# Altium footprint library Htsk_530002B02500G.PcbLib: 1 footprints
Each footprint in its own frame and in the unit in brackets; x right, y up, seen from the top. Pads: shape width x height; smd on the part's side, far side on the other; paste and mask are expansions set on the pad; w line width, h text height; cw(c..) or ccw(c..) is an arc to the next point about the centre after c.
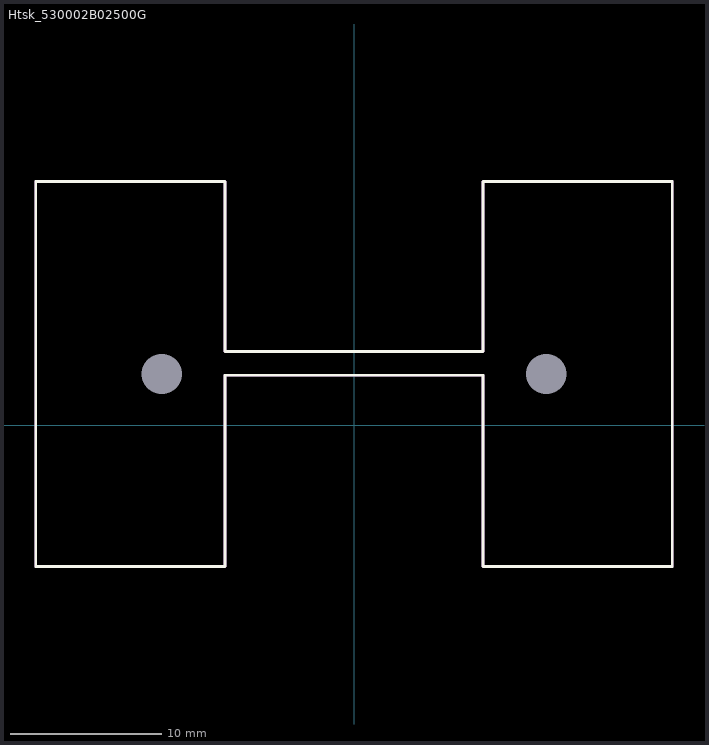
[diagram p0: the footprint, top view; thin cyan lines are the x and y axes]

## Htsk_530002B02500G [mm]
height 63.5
pads (2):
  round 0 hole 2.67 unplated mask+0: 0(-12.7,3.381) 0(12.7,3.381)
Top Overlay:
  lines w0.178: -20.995,-9.319 -20.995,16.081 -8.51,16.081 -8.51,4.872 8.51,4.872 8.51,16.081 20.995,16.081 20.995,-9.319 8.51,-9.319 8.51,3.302 -8.51,3.302 -8.51,-9.319 -20.995,-9.319
M5 Assembly Top:
  text ".Designator" at -1.524,2.873 h1.02
M13 Component Bodies Top:
  lines w0.178: -20.995,-9.319 -8.51,-9.319 -8.51,3.302 8.51,3.302 8.51,-9.319 20.995,-9.319 20.995,16.081 8.51,16.081 8.51,4.872 -8.51,4.872 -8.51,16.081 -20.995,16.081 -20.995,-9.319
3D body: height 63.5, standoff 0, extent -20.995,-9.319 20.995,16.081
